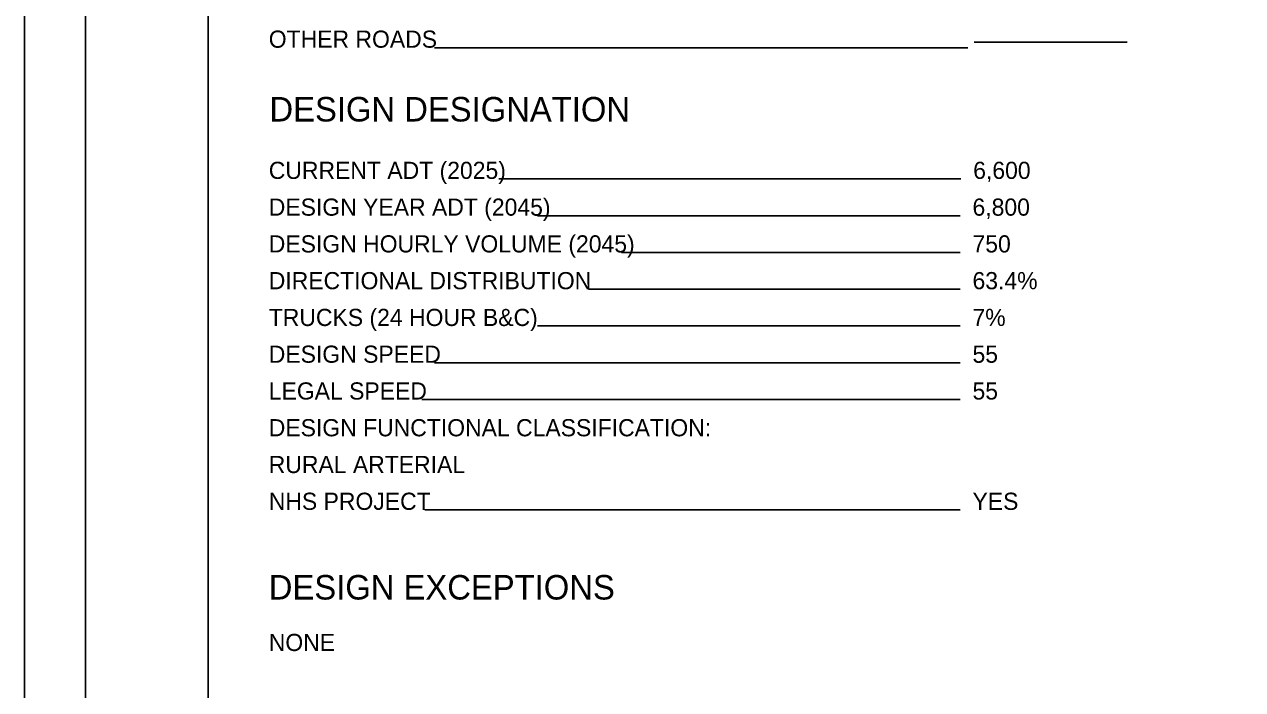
# Model space of a CAD drawing. Extents: x 0 to 34, y 0 to 22.
# Drawn here: x 0 to 9.94, y 5.64 to 11.07 of the extents above; entities that cross this region are included whole.
import ezdxf

# ---------------------------------------------------------------- set-up
doc = ezdxf.new("R2010")
doc.units = 0
for name, color, linetype in [('SH_Border', 7, 'Continuous'), ('SH_Cut_Line', 7, 'Continuous'), ('SH_Data', 7, 'Continuous'), ('SH_Text', 7, 'Continuous')]:
    doc.layers.add(name, color=color, linetype=linetype)

msp = doc.modelspace()

# ---------------------------------------------------------------- linework, layer by layer
at = {"layer": 'SH_Border'}
for points in [[(0.5, 21.5), (1.5, 21.5), (1.5, 0.5), (0.5, 0.5)], [(1.5, 21.5), (33.5, 21.5), (33.5, 0.5), (1.5, 0.5)]]:
    msp.add_lwpolyline(points, close=True, dxfattribs=at)
at = {"layer": 'SH_Cut_Line'}
msp.add_lwpolyline([(0, 0), (34, 0), (34, 22), (0, 22)], close=True, dxfattribs=at)
at = {"layer": 'SH_Data'}
for p, q in [((7.7, 10.8767), (3.3471, 10.8767)), ((9, 10.9223), (7.75, 10.9223)), ((7.6424, 9.8062), (3.871, 9.8062)), ((7.6368, 9.5062), (4.1885, 9.5062)), ((7.6368, 9.2062), (4.8723, 9.2062)), ((7.6368, 8.9062), (4.6037, 8.9062)), ((7.6368, 8.6062), (4.1885, 8.6062)), ((7.6368, 8.3062), (3.346, 8.3062)), ((7.6368, 8.0062), (3.2422, 8.0062)), ((7.6368, 7.1062), (3.2669, 7.1062))]:
    msp.add_line(p, q, dxfattribs=at)

# ---------------------------------------------------------------- texts
msp.add_text('DESIGN DESIGNATION', height=0.2, dxfattribs=at).set_placement((2, 10.2747))
at = {"layer": 'SH_Text'}
for s, height, p in [('OTHER ROADS', 0.14, (1.9944, 10.8767)), ('CURRENT ADT (2025)', 0.14, (1.9944, 9.8062)), ('6,600', 0.14, (7.7424, 9.8062)), ('DESIGN YEAR ADT (2045)', 0.14, (1.9944, 9.5062)), ('6,800', 0.14, (7.7368, 9.5062)), ('DESIGN HOURLY VOLUME (2045)', 0.14, (1.9944, 9.2062)), ('750', 0.14, (7.7368, 9.2062)), ('DIRECTIONAL DISTRIBUTION', 0.14, (1.9944, 8.9062)), ('63.4%', 0.14, (7.7368, 8.9062)), ('TRUCKS (24 HOUR B&C)', 0.14, (1.9944, 8.6062)), ('7%', 0.14, (7.7368, 8.6062)), ('DESIGN SPEED', 0.14, (1.9944, 8.3062)), ('55', 0.14, (7.7368, 8.3062)), ('LEGAL SPEED', 0.14, (1.9944, 8.0062)), ('55', 0.14, (7.7368, 8.0062)), ('DESIGN FUNCTIONAL CLASSIFICATION:', 0.14, (1.9944, 7.7062)), ('RURAL ARTERIAL', 0.14, (1.9944, 7.4062)), ('NHS PROJECT', 0.14, (1.9944, 7.1062)), ('YES', 0.14, (7.7368, 7.1062)), ('DESIGN EXCEPTIONS', 0.2, (1.9944, 6.3744)), ('NONE', 0.14, (1.9944, 5.9544))]:
    msp.add_text(s, height=height, dxfattribs=at).set_placement(p)

doc.saveas('drawing.dxf')
